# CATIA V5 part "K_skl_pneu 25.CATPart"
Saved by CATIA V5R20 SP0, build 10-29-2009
Part number: skl_pneu 25
Publications: "longueur axe pivot", "Plan.+100", "pneu 25", "Droite.1"
Bounding box of the stored display mesh (mm): x 100 to 250, y 1060 to 1060, z 0 to 0
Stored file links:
  G:\Khaled_CFAO_2011\SIL\SIL_GR2\mdardier\Khaled\CAD_ThinkMOTION\K_skl_pneu 25.CATPart
  G:\Khaled_CFAO_2011\SIL\SIL_GR2\mdardier\Khaled\CAD_ThinkMOTION\K_skl_ass_tandem.CATProduct
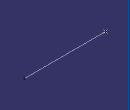
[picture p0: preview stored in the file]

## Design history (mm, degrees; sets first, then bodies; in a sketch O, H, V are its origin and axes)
External parameters (linked from other documents)
  `External.longueur axe pivot` = 150 mm
Set1
  Plane1 "Plan.+100": linked copy from another document
  Point1 "pneu 25": linked copy from another document
Set2
  Line1: type Normal, RefPoint Point1, RefSkin Plane1, Start 0, End 150 {= `External.longueur axe pivot`}
Body1 (main body)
